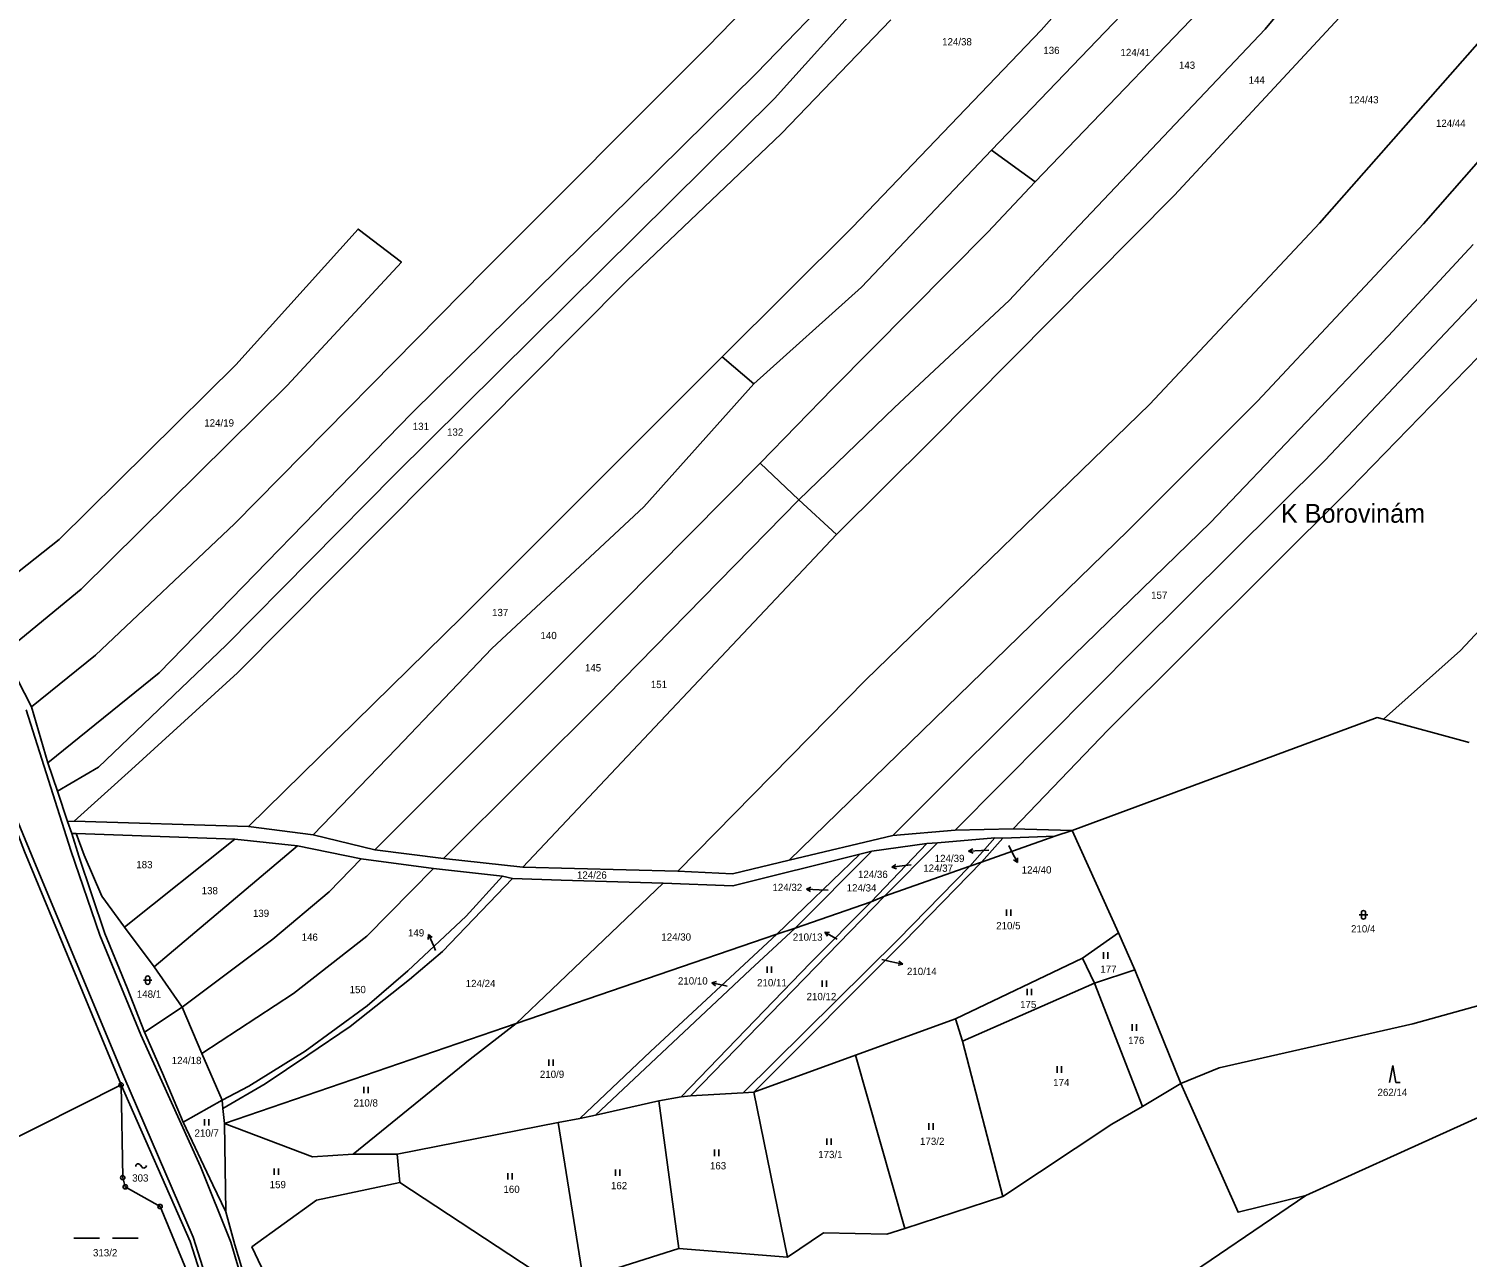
# Model space of a CAD drawing. Extents: x -680203 to -673936, y -1102717 to -1093650.
# Drawn here: x -676284.4 to -675948.1, y -1101570.7 to -1101283.6 of the extents above; entities that cross this region are included whole.
import ezdxf

# ---------------------------------------------------------------- set-up
doc = ezdxf.new("R2010")
doc.units = 0
for name, color, linetype in [('SOxx02xx_Koleje_param další_Popis10', 7, 'Continuous'), ('SOxx02xx_Staničení_Popis10', 7, 'Continuous'), ('SOxxxxxx_Koleje_hlavní_body_Popis10', 7, 'Continuous'), ('SOxxxxxx_Koleje_param další_Popis10', 7, 'Continuous'), ('SOxxxxxx_Osa_bod_P', 7, 'Continuous'), ('SOxxxxxx_Staničení_Popis10', 7, 'Continuous'), ('x_prac', 7, 'Continuous')]:
    doc.layers.add(name, color=color, linetype=linetype)

msp = doc.modelspace()

# ---------------------------------------------------------------- linework, layer by layer
at = {"layer": 'SOxx02xx_Koleje_param další_Popis10'}
for centre, radius in [((-676262.78, -1101530.48), 0.5), ((-676262.78, -1101530.48), 0.0303), ((-676262.4, -1101552.12), 0.5), ((-676262.4, -1101552.12), 0.0303), ((-676261.8, -1101554.29), 0.5), ((-676261.8, -1101554.29), 0.0303), ((-676253.67, -1101558.89), 0.5), ((-676253.67, -1101558.89), 0.0303)]:
    msp.add_circle(centre, radius, dxfattribs=at)
at = {"layer": 'SOxx02xx_Staničení_Popis10'}
for p, q in [((-676064.68, -1101475.82), (-676063.7, -1101475.27)), ((-676061.68, -1101475.66), (-676064.68, -1101475.82)), ((-676064.68, -1101475.82), (-676063.65, -1101476.27)), ((-676059.99, -1101475.57), (-676061.68, -1101475.66)), ((-676055.29, -1101474.54), (-676054.64, -1101475.82)), ((-676054.64, -1101475.82), (-676053.28, -1101478.49)), ((-676053.28, -1101478.49), (-676054.18, -1101477.83)), ((-676053.28, -1101478.49), (-676053.29, -1101477.37)), ((-676082.61, -1101479.56), (-676081.68, -1101478.94)), ((-676079.63, -1101479.19), (-676082.61, -1101479.56)), ((-676082.61, -1101479.56), (-676081.55, -1101479.93)), ((-676078.1, -1101479), (-676079.63, -1101479.19)), ((-676102.6, -1101484.71), (-676101.57, -1101484.27)), ((-676099.6, -1101484.87), (-676102.6, -1101484.71)), ((-676102.6, -1101484.71), (-676101.62, -1101485.27)), ((-676097.54, -1101484.97), (-676099.6, -1101484.87)), ((-676190.94, -1101495.34), (-676190.99, -1101496.46)), ((-676189.72, -1101498.08), (-676190.94, -1101495.34)), ((-676190.94, -1101495.34), (-676190.08, -1101496.05)), ((-676095.69, -1101496.26), (-676098.29, -1101494.76)), ((-676098.29, -1101494.76), (-676097.17, -1101494.83)), ((-676098.29, -1101494.76), (-676097.67, -1101495.69)), ((-676095.44, -1101496.4), (-676095.69, -1101496.26)), ((-676189.29, -1101499.06), (-676189.72, -1101498.08)), ((-676084.98, -1101501.19), (-676083.03, -1101501.6)), ((-676083.03, -1101501.6), (-676080.09, -1101502.22)), ((-676080.09, -1101502.22), (-676081.18, -1101502.51)), ((-676080.09, -1101502.22), (-676080.97, -1101501.53)), ((-676124.7, -1101506.6), (-676123.62, -1101506.31)), ((-676121.77, -1101507.22), (-676124.7, -1101506.6)), ((-676124.7, -1101506.6), (-676123.83, -1101507.29)), ((-676121.1, -1101507.37), (-676121.77, -1101507.22))]:
    msp.add_line(p, q, dxfattribs=at)
at = {"layer": 'SOxxxxxx_Koleje_hlavní_body_Popis10'}
for p, q in [((-676055.8, -1101490.98), (-676055.8, -1101489.48)), ((-676054.8, -1101490.98), (-676054.8, -1101489.48)), ((-675973.39, -1101490.72), (-675971.39, -1101490.72)), ((-675972.89, -1101490.22), (-675972.89, -1101491.22)), ((-675971.89, -1101491.22), (-675971.89, -1101490.22)), ((-676033.13, -1101500.97), (-676033.13, -1101499.47)), ((-676032.13, -1101500.97), (-676032.13, -1101499.47)), ((-676111.74, -1101504.3), (-676111.74, -1101502.8)), ((-676110.74, -1101504.3), (-676110.74, -1101502.8)), ((-676257.56, -1101505.98), (-676255.56, -1101505.98)), ((-676257.06, -1101505.48), (-676257.06, -1101506.48)), ((-676256.06, -1101506.48), (-676256.06, -1101505.48)), ((-676098.88, -1101507.54), (-676098.88, -1101506.04)), ((-676097.88, -1101507.54), (-676097.88, -1101506.04)), ((-676050.98, -1101509.52), (-676050.98, -1101508.02)), ((-676049.98, -1101509.52), (-676049.98, -1101508.02)), ((-676026.43, -1101517.8), (-676026.43, -1101516.3)), ((-676025.43, -1101517.8), (-676025.43, -1101516.3)), ((-676162.8, -1101526.02), (-676162.8, -1101524.52)), ((-676161.8, -1101526.02), (-676161.8, -1101524.52)), ((-676043.95, -1101527.62), (-676043.95, -1101526.12)), ((-676042.95, -1101527.62), (-676042.95, -1101526.12)), ((-675965.55, -1101525.94), (-675966.3, -1101529.94)), ((-675964.8, -1101529.94), (-675965.55, -1101525.94)), ((-676206.02, -1101532.41), (-676206.02, -1101530.91)), ((-676205.02, -1101532.41), (-676205.02, -1101530.91)), ((-675964.8, -1101529.94), (-675963.8, -1101529.94)), ((-676243.3, -1101539.96), (-676243.3, -1101538.46)), ((-676242.3, -1101539.96), (-676242.3, -1101538.46)), ((-676073.96, -1101540.95), (-676073.96, -1101539.45)), ((-676072.96, -1101540.95), (-676072.96, -1101539.45)), ((-676097.79, -1101544.46), (-676097.79, -1101542.96)), ((-676096.79, -1101544.46), (-676096.79, -1101542.96)), ((-676124.07, -1101547.09), (-676124.07, -1101545.59)), ((-676123.07, -1101547.09), (-676123.07, -1101545.59)), ((-676227, -1101551.49), (-676227, -1101549.99)), ((-676226, -1101551.49), (-676226, -1101549.99)), ((-676172.38, -1101552.58), (-676172.38, -1101551.08)), ((-676171.38, -1101552.58), (-676171.38, -1101551.08)), ((-676147.22, -1101551.74), (-676147.22, -1101550.24)), ((-676146.22, -1101551.74), (-676146.22, -1101550.24)), ((-676273.8, -1101566.26), (-676267.8, -1101566.26)), ((-676264.8, -1101566.26), (-676258.8, -1101566.26))]:
    msp.add_line(p, q, dxfattribs=at)
for centre, start, end in [((-675972.39, -1101490.22), 0, 180), ((-675972.39, -1101491.22), 180, 359.9879), ((-676256.56, -1101505.48), 0, 180), ((-676256.56, -1101506.48), 180, 359.9879)]:
    msp.add_arc(centre, 0.5, start, end, dxfattribs=at)
at = {"layer": 'SOxxxxxx_Koleje_param další_Popis10'}
msp.add_line((-676258.27, -1101549.21), (-676257.97, -1101549.61), dxfattribs=at)
for centre, start, end in [((-676258.78, -1101549.5), 29.2914, 181.2189), ((-676257.46, -1101549.32), 209.2914, 1.2189)]:
    msp.add_arc(centre, 0.588, start, end, dxfattribs=at)
at = {"layer": 'SOxxxxxx_Staničení_Popis10'}
for p, q in [((-676274.52, -1101475.72), (-676284.96, -1101442.82)), ((-676290.52, -1101460.23), (-676282.6, -1101479.33)), ((-676274.52, -1101475.72), (-676267.78, -1101495.46)), ((-676282.6, -1101479.33), (-676262.16, -1101528.54)), ((-676267.78, -1101495.46), (-676258.14, -1101518.78)), ((-676258.14, -1101518.78), (-676244.22, -1101549.57)), ((-676245.93, -1101566.09), (-676262.16, -1101528.54)), ((-676244.22, -1101549.57), (-676237.1, -1101567.26)), ((-676237.98, -1101590.75), (-676245.93, -1101566.09)), ((-676232.01, -1101584.68), (-676237.1, -1101567.26))]:
    msp.add_line(p, q, dxfattribs=at)
at = {"layer": 'x_prac'}
for p, q in [((-676059.3, -1101312), (-676049.16, -1101319.44)), ((-676122.29, -1101360.29), (-676114.86, -1101366.63)), ((-676113.38, -1101385.16), (-676104.38, -1101393.69)), ((-676104.38, -1101393.69), (-676095.54, -1101401.83)), ((-676095.54, -1101401.83), (-676168.89, -1101479.58)), ((-676290.18, -1101429.46), (-676283.76, -1101442.09)), ((-676279.9, -1101455.2), (-676283.76, -1101442.09)), ((-675947.71, -1101450.41), (-675967.71, -1101445.01)), ((-676277.63, -1101461.85), (-676279.9, -1101455.2)), ((-676275.28, -1101468.92), (-676277.63, -1101461.85)), ((-676273.72, -1101468.8), (-676275.28, -1101468.92)), ((-676274.33, -1101471.73), (-676275.28, -1101468.92)), ((-676232.98, -1101470.05), (-676273.72, -1101468.8)), ((-676217.87, -1101472.01), (-676232.98, -1101470.05)), ((-676067.85, -1101470.96), (-676082.37, -1101472.21)), ((-676054.25, -1101470.63), (-676067.85, -1101470.96)), ((-676040.45, -1101470.99), (-676054.25, -1101470.63)), ((-676040.45, -1101470.99), (-676044.53, -1101472.37)), ((-676040.45, -1101470.99), (-676029.67, -1101494.95)), ((-676273.31, -1101471.73), (-676274.33, -1101471.73)), ((-676273.31, -1101471.73), (-676236.22, -1101473.05)), ((-676236.22, -1101473.05), (-676261.96, -1101493.62)), ((-676236.22, -1101473.05), (-676221.53, -1101474.61)), ((-676203.47, -1101475.55), (-676217.87, -1101472.01)), ((-676082.37, -1101472.21), (-676106.59, -1101477.96)), ((-676087.44, -1101487.65), (-676074.44, -1101474.04)), ((-676087.27, -1101475.82), (-676074.44, -1101474.04)), ((-676084.36, -1101486.37), (-676071.94, -1101473.88)), ((-676074.44, -1101474.04), (-676071.94, -1101473.88)), ((-676071.94, -1101473.88), (-676058.53, -1101472.76)), ((-676064.42, -1101479.37), (-676058.53, -1101472.76)), ((-676044.53, -1101472.37), (-676061.66, -1101478.38)), ((-676061.66, -1101478.38), (-676056.68, -1101472.77)), ((-676058.53, -1101472.76), (-676056.68, -1101472.77)), ((-676056.68, -1101472.77), (-676044.53, -1101472.37)), ((-676255.03, -1101502.88), (-676221.53, -1101474.61)), ((-676221.53, -1101474.61), (-676206.67, -1101477.67)), ((-676206.67, -1101477.67), (-676189.79, -1101479.92)), ((-676187.43, -1101477.53), (-676203.47, -1101475.55)), ((-676168.89, -1101479.58), (-676187.43, -1101477.53)), ((-676109.55, -1101495.27), (-676090.09, -1101476.56)), ((-676105.25, -1101493.86), (-676087.27, -1101475.82)), ((-676090.09, -1101476.56), (-676087.27, -1101475.82)), ((-676189.79, -1101479.92), (-676173.67, -1101481.72)), ((-676132.62, -1101480.53), (-676168.89, -1101479.58)), ((-676084.36, -1101486.37), (-676064.42, -1101479.37)), ((-676064.42, -1101479.37), (-676061.66, -1101478.38)), ((-676173.67, -1101481.72), (-676171.33, -1101482.19)), ((-676084.36, -1101486.37), (-676129.68, -1101533.04)), ((-676105.25, -1101493.86), (-676087.44, -1101487.65)), ((-676087.44, -1101487.65), (-676084.36, -1101486.37)), ((-676255.03, -1101502.88), (-676261.96, -1101493.62)), ((-676109.55, -1101495.27), (-676105.25, -1101493.86)), ((-676170.46, -1101516.13), (-676109.55, -1101495.27)), ((-676038.09, -1101500.84), (-676029.67, -1101494.95)), ((-676029.67, -1101494.95), (-676025.84, -1101503.55)), ((-676067.76, -1101515.01), (-676038.09, -1101500.84)), ((-676035.26, -1101506.66), (-676038.09, -1101500.84)), ((-676248.54, -1101512.28), (-676255.03, -1101502.88)), ((-676025.84, -1101503.55), (-676035.26, -1101506.66)), ((-676025.84, -1101503.55), (-676015.05, -1101530.13)), ((-676035.26, -1101506.66), (-676066.08, -1101520.28)), ((-676024.08, -1101535.48), (-676035.26, -1101506.66)), ((-676257.33, -1101518.11), (-676248.54, -1101512.28)), ((-676243.87, -1101523.12), (-676248.54, -1101512.28)), ((-676238.63, -1101539.5), (-676170.46, -1101516.13)), ((-676091.12, -1101523.53), (-676067.76, -1101515.01)), ((-676066.08, -1101520.28), (-676067.76, -1101515.01)), ((-676056.65, -1101556.52), (-676066.08, -1101520.28)), ((-676239.13, -1101534.03), (-676243.87, -1101523.12)), ((-676114.86, -1101532.17), (-676091.12, -1101523.53)), ((-676079.62, -1101564.03), (-676091.12, -1101523.53)), ((-676262.78, -1101530.48), (-676292.81, -1101545.54)), ((-676262.4, -1101552.12), (-676262.78, -1101530.48)), ((-676015.05, -1101530.13), (-676024.08, -1101535.48)), ((-676248.26, -1101539.15), (-676239.13, -1101534.03)), ((-676239.13, -1101534.03), (-676239.01, -1101535.99)), ((-676137.08, -1101534.21), (-676151.93, -1101537.58)), ((-676131.84, -1101533.23), (-676137.08, -1101534.21)), ((-676132.43, -1101568.74), (-676137.08, -1101534.21)), ((-676129.68, -1101533.04), (-676131.84, -1101533.23)), ((-676117.35, -1101532.3), (-676129.68, -1101533.04)), ((-676114.86, -1101532.17), (-676117.35, -1101532.3)), ((-676107.05, -1101570.71), (-676114.86, -1101532.17)), ((-676239.01, -1101535.99), (-676238.63, -1101539.5)), ((-676155.59, -1101538.29), (-676160.62, -1101539.26)), ((-676151.93, -1101537.58), (-676155.59, -1101538.29)), ((-676238.63, -1101539.5), (-676238.31, -1101560.1)), ((-676160.62, -1101539.26), (-676198.28, -1101546.65)), ((-676154.74, -1101575.83), (-676160.62, -1101539.26)), ((-676198.28, -1101546.65), (-676208.5, -1101546.69)), ((-676197.62, -1101553.26), (-676198.28, -1101546.65)), ((-676160.79, -1101577.49), (-676197.62, -1101553.26)), ((-676131.26, -1101655.21), (-675985.9, -1101556.28)), ((-676056.65, -1101556.52), (-676079.62, -1101564.03)), ((-676243.62, -1101583.02), (-676253.67, -1101558.89)), ((-676132.43, -1101568.74), (-676154.74, -1101575.83)), ((-676107.05, -1101570.71), (-676132.43, -1101568.74))]:
    msp.add_line(p, q, dxfattribs=at)
for points in [[(-676283.76, -1101442.09), (-676268.78, -1101430.05), (-676236.24, -1101399.36), (-676177.73, -1101339.95), (-676125.69, -1101287.83), (-676087.97, -1101249.07), (-676059.88, -1101216.55), (-676032.1, -1101182.52), (-675982.61, -1101112.4), (-675965.2, -1101086.82)], [(-676132.62, -1101480.53), (-676088.79, -1101435.89), (-676022.36, -1101371.38), (-675982.71, -1101329.03), (-675929.09, -1101268.11), (-675906.41, -1101239.03), (-675889.22, -1101212.54), (-675858.31, -1101161.13), (-675840.95, -1101133.29)], [(-676106.59, -1101477.96), (-676027.48, -1101400.98), (-675997.13, -1101370.63), (-675958.35, -1101329.21), (-675922.61, -1101288.47), (-675902.82, -1101263.42), (-675888.06, -1101242.43), (-675860.54, -1101199.14), (-675824.23, -1101141.68)], [(-676054.25, -1101470.63), (-676032.07, -1101447.5), (-675975.6, -1101391.24), (-675945.62, -1101360.36), (-675908.85, -1101321.52), (-675887.74, -1101294.71), (-675859.74, -1101255.79), (-675819.21, -1101192), (-675796.48, -1101155.74)], [(-675967.71, -1101445.01), (-675949.73, -1101428.92), (-675878.43, -1101352.75), (-675852.84, -1101319.46), (-675835.55, -1101295.31), (-675748.75, -1101166.81)], [(-676049.16, -1101319.44), (-676001.37, -1101269.6), (-675968.37, -1101231.06), (-675942.76, -1101194.73)], [(-676104.38, -1101393.69), (-676081.99, -1101372.18), (-676055.21, -1101347.12), (-676040.16, -1101331.01), (-675995.38, -1101283.7), (-675956.05, -1101236.36), (-675931.93, -1101201.98)], [(-676122.29, -1101360.29), (-676091.81, -1101330), (-676047.72, -1101283.97), (-676005.88, -1101236.84), (-675983.53, -1101210.04), (-675978.57, -1101202.63), (-675968.95, -1101207.48)], [(-675921, -1101206.93), (-675926.63, -1101216.31), (-675949.5, -1101247.2), (-675977.02, -1101279.94), (-676016.61, -1101322.59), (-676073.4, -1101379.85), (-676095.54, -1101401.83)], [(-675968.95, -1101207.48), (-675977.63, -1101219.92), (-675997.89, -1101244.29), (-676029, -1101280.48), (-676059.3, -1101312)], [(-676279.9, -1101455.2), (-676253.85, -1101434.14), (-676194.91, -1101373.57), (-676114.26, -1101293.98), (-676093.34, -1101272.26)], [(-676277.63, -1101461.85), (-676268.1, -1101456.23), (-676238.2, -1101427.7), (-676198.82, -1101387.77), (-676110.04, -1101299.93), (-676089.28, -1101276.79)], [(-676082.86, -1101281.53), (-676108.39, -1101308.1), (-676144.53, -1101342.45), (-676235.54, -1101434.12), (-676260.32, -1101456.75), (-676273.72, -1101468.8)], [(-676114.86, -1101366.63), (-676089.73, -1101344.01), (-676059.3, -1101312)], [(-676113.38, -1101385.16), (-676096.39, -1101367.72), (-676060.18, -1101331.18), (-676049.16, -1101319.44)], [(-676296.03, -1101417.83), (-676277.22, -1101402.96), (-676235.95, -1101362.16), (-676207.38, -1101330.44), (-676197.27, -1101338.19), (-676223.93, -1101366.99), (-676272.11, -1101414.58), (-676290.18, -1101429.46)], [(-676082.37, -1101472.21), (-676042.73, -1101432.62), (-676008.14, -1101399.05), (-675966.57, -1101355.43), (-675946.72, -1101334.07)], [(-675938.46, -1101339.08), (-675981.42, -1101384.51), (-676025.11, -1101427.95), (-676067.85, -1101470.96)], [(-676232.98, -1101470.05), (-676183.05, -1101421.08), (-676122.29, -1101360.29)], [(-676217.87, -1101472.01), (-676198.37, -1101451.87), (-676176.15, -1101428.49), (-676140.6, -1101395.36), (-676114.86, -1101366.63)], [(-676203.47, -1101475.55), (-676146.22, -1101418.26), (-676113.38, -1101385.16)], [(-676187.43, -1101477.53), (-676149.28, -1101439.54), (-676104.38, -1101393.69)], [(-675967.71, -1101445.01), (-675969.2, -1101444.61), (-676040.45, -1101470.99)], [(-676290.83, -1101461.65), (-676285.38, -1101475.9), (-676262.78, -1101530.48)], [(-676274.33, -1101471.73), (-676272.69, -1101476.97), (-676266.6, -1101495.07), (-676261.36, -1101507.81), (-676257.33, -1101518.11)], [(-676261.96, -1101493.62), (-676267.29, -1101486.32), (-676271.39, -1101476.75), (-676273.31, -1101471.73)], [(-676248.54, -1101512.28), (-676227.33, -1101496.43), (-676214.18, -1101485.31), (-676206.67, -1101477.67)], [(-676136.07, -1101483.35), (-676119.79, -1101483.98), (-676090.09, -1101476.56)], [(-676243.87, -1101523.12), (-676222.47, -1101509.11), (-676205.32, -1101495.7), (-676189.79, -1101479.92)], [(-676106.59, -1101477.96), (-676119.9, -1101481.11), (-676132.62, -1101480.53)], [(-676117.35, -1101532.3), (-676081.25, -1101496.54), (-676064.42, -1101479.37)], [(-676061.66, -1101478.38), (-676079.81, -1101497.06), (-676114.86, -1101532.17)], [(-676173.67, -1101481.72), (-676182.09, -1101491.04), (-676195.79, -1101503.79), (-676205.29, -1101511.98), (-676219.77, -1101522.57), (-676232.95, -1101530.74), (-676239.13, -1101534.03)], [(-676171.33, -1101482.19), (-676187.65, -1101499.29), (-676195.35, -1101505.84), (-676209.25, -1101516.84), (-676219.1, -1101523.51), (-676229.11, -1101530.2), (-676239.01, -1101535.99)], [(-676136.07, -1101483.35), (-676159.94, -1101482.62), (-676171.33, -1101482.19)], [(-676170.46, -1101516.13), (-676162.12, -1101508.2), (-676136.07, -1101483.35)], [(-676131.84, -1101533.23), (-676101.63, -1101501.94), (-676087.44, -1101487.65)], [(-676151.93, -1101537.58), (-676115.76, -1101503.54), (-676105.25, -1101493.86)], [(-676155.59, -1101538.29), (-676139.06, -1101522.68), (-676109.55, -1101495.27)], [(-676015.05, -1101530.13), (-676006.1, -1101526.51), (-675960.82, -1101516.19), (-675945.45, -1101511.91), (-675928.69, -1101517.85), (-675919.16, -1101518.98)], [(-676248.26, -1101539.15), (-676253.07, -1101527.72), (-676257.33, -1101518.11)], [(-676208.5, -1101546.69), (-676181.22, -1101524.44), (-676170.46, -1101516.13)], [(-675919.16, -1101518.98), (-675918.38, -1101525.79), (-675985.9, -1101556.28)], [(-676262.78, -1101530.48), (-676246.63, -1101567.03), (-676239.27, -1101590.25)], [(-675985.9, -1101556.28), (-676001.72, -1101560.23), (-676015.05, -1101530.13)], [(-676024.08, -1101535.48), (-676031.23, -1101539.64), (-676056.65, -1101556.52)], [(-676238.31, -1101560.1), (-676241.32, -1101553.86), (-676248.26, -1101539.15)], [(-676208.5, -1101546.69), (-676218.08, -1101547.28), (-676238.63, -1101539.5)], [(-676253.67, -1101558.89), (-676261.8, -1101554.29), (-676262.4, -1101552.12)], [(-676197.62, -1101553.26), (-676217.14, -1101557.44), (-676232.21, -1101568.32), (-676217.77, -1101598.59), (-676203.06, -1101605.09)], [(-676204.65, -1101605.85), (-676220.02, -1101599.57), (-676231.26, -1101584.07), (-676236.16, -1101567.85), (-676238.31, -1101560.1)], [(-676079.62, -1101564.03), (-676083.83, -1101565.32), (-676098.59, -1101565.01), (-676107.05, -1101570.71)]]:
    msp.add_lwpolyline(points, dxfattribs=at)

# ---------------------------------------------------------------- texts
at = {"layer": 'SOxx02xx_Staničení_Popis10'}
msp.add_text('K Borovinám', height=4.4, dxfattribs=at).set_placement((-675991.68, -1101399.08))
at = {"layer": 'SOxxxxxx_Osa_bod_P'}
for s, p in [('124/38', (-676070.88, -1101287.52)), ('136', (-676047.22, -1101289.53)), ('124/41', (-676029.18, -1101290.02)), ('143', (-676015.53, -1101292.99)), ('144', (-675999.24, -1101296.46)), ('124/43', (-675975.83, -1101301.06)), ('124/44', (-675955.46, -1101306.56)), ('124/19', (-676243.34, -1101376.59)), ('131', (-676194.61, -1101377.41)), ('132', (-676186.59, -1101378.74)), ('157', (-676022.03, -1101416.86)), ('137', (-676176.07, -1101420.91)), ('140', (-676164.75, -1101426.29)), ('145', (-676154.37, -1101433.83)), ('151', (-676138.97, -1101437.72)), ('124/39', (-676072.61, -1101478.39)), ('183', (-676259.23, -1101479.83)), ('124/26', (-676156.22, -1101482.27)), ('124/36', (-676090.54, -1101482.11)), ('124/37', (-676075.29, -1101480.66)), ('124/40', (-676052.28, -1101481.06)), ('138', (-676243.95, -1101485.91)), ('124/32', (-676110.53, -1101485.16)), ('124/34', (-676093.19, -1101485.26)), ('139', (-676231.97, -1101491.21)), ('149', (-676195.72, -1101495.77)), ('210/5', (-676058.24, -1101494.1)), ('210/4', (-675975.3, -1101494.84)), ('146', (-676220.58, -1101496.78)), ('124/30', (-676136.51, -1101496.75)), ('210/13', (-676105.78, -1101496.77)), ('210/14', (-676079.1, -1101504.79)), ('177', (-676033.9, -1101504.27)), ('150', (-676209.37, -1101509.03)), ('124/24', (-676182.24, -1101507.62)), ('210/10', (-676132.63, -1101507.01)), ('210/11', (-676114.13, -1101507.43)), ('148/1', (-676259.1, -1101510.1)), ('210/12', (-676102.56, -1101510.67)), ('175', (-676052.65, -1101512.52)), ('176', (-676027.4, -1101520.93)), ('124/18', (-676250.95, -1101525.61)), ('210/9', (-676164.9, -1101528.83)), ('174', (-676044.92, -1101530.75)), ('262/14', (-675969.11, -1101533.06)), ('210/8', (-676208.44, -1101535.53)), ('210/7', (-676245.62, -1101542.56)), ('173/2', (-676076.04, -1101544.5)), ('173/1', (-676099.84, -1101547.58)), ('303', (-676260.19, -1101553.07)), ('163', (-676125.15, -1101550.22)), ('159', (-676228.05, -1101554.61)), ('160', (-676173.41, -1101555.71)), ('162', (-676148.29, -1101554.86)), ('313/2', (-676269.35, -1101570.55))]:
    msp.add_text(s, height=1.7, dxfattribs=at).set_placement(p)

doc.saveas('drawing.dxf')
